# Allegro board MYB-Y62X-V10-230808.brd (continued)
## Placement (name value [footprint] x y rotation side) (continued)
TP5  SMD  [TEST0_8-SMD]  42.08 79.88 0 top
TP6  SMD  [TEST0_8-SMD]  35.84 30.94 0 top
TP7  SMD  [HOLE-TP0_9S16]  47.34 42.34 0 top
TP8  SMD  [TEST0_8-SMD]  37.77 34.16 0 top
TP9  SMD  [HOLE-TP0_9S16]  60.7 44.3 0 top
TP10  SMD  [HOLE-TP0_9S16]  87.55 100.97 0 top
TP14  SMD  [TEST0_8-SMD]  127.17 19.15 0 top
TP15  -  [TPAD_020]  65.99 102.31 0 bottom
TP16  -  [TPAD_020]  74.21 106.51 0 bottom
TP17  SMD  [HOLE-TP0_9S16]  34.46 67.06 0 top
TP18  -  [TPAD_020]  26.97 47.62 180 bottom
TP19  -  [TPAD_020]  32.56 47.62 180 bottom
TP20  -  [TPAD_020]  33.57 47.62 180 bottom
TP21  -  [TPAD_020]  34.59 47.62 0 bottom
TP22  -  [TPAD_020]  39.16 47.62 180 bottom
TP23  -  [TPAD_020]  40.18 47.62 180 bottom
TP24  -  [TPAD_020]  41.19 47.62 180 bottom
TP25  -  [TPAD_020]  42.21 47.62 180 bottom
TP26  -  [TPAD_020]  43.23 47.62 180 bottom
TP27  -  [TPAD_020]  44.5 47.62 180 bottom
TP28  -  [TPAD_020]  45.77 47.62 180 bottom
TP30  SMD  [HOLE-TP0_9S16]  28.88 67.06 0 top
TP31  SMD  [HOLE-TP0_9S16]  83.61 94.87 0 top
TP32  SMD  [HOLE-TP0_9S16]  42.46 35.31 0 top
TP33  SMD  [HOLE-TP0_9S16]  60.73 40.34 0 top
U1  SY8388ARHC  [QFN16_0_45]  38.53 81.15 0 top
U2  SY8388ARHC  [QFN16_0_45]  34.21 35.43 0 top
U3  MP2143DJ-LF-Z  [TSOT23-8]  52.37 39.12 0 top
U4  MP2143DJ-LF-Z  [TSOT23-8]  77.14 96.65 0 top
U8  RS1G08XF5  [SOT23-5]  94.15 112.39 180 top
U12  RS1G32XC5  [SC70-5]  156.26 85.09 0 top
U13  RS1G32XC5  [SC70-5]  156.26 81.28 0 top
U14  PCMF2USB3S  [WLCSP10]  19.73 55.5 90 top
U15  PCMF2USB3S  [WLCSP10]  19.73 67.94 90 top
U16  PCMF3USB3S/CZ  [WLCSP15]  19.73 61.59 90 top
U17  PCMF3USB3S/CZ  [WLCSP15]  19.73 74.17 90 top
U18  RS0102YVS8  [VSSOP8]  156.26 69.47 0 top
U19  CH342F  [QFN24-0_5]  71.11 19.68 90 top
U20  NSI1050-DDBR  [SOP8-2_54]  156.44 100.6 0 top
U21  B0505S-1WR3  [MODULE-B0505S]  166.1 100.6 270 top
U22  NSI1050-DDBR  [SOP8-2_54]  145.01 100.48 0 top
U23  NSI83085A  [SOIC16-W]  132.31 100.48 90 top
U24  B0505S-1WR3  [MODULE-B0505S]  108.06 101.37 270 top
U25  NSI83085A  [SOIC16-W]  119.61 100.48 90 top
U27  SGTL5000XNAA3  [QFN32]  44.75 21.97 0 top
U28  FE1.1-AQFP48AT  [LQFP48]  130.86 29.59 0 top
U29  PTN5150AHXMP  [X2QFN12]  58.21 18.8 90 top
U30  MP62055EJ-LF-Z  [SOT23-5]  59.61 25.4 180 top
U31  SM8103ADC  [SOT23-6]  38.4 65.15 0 top
U32  SR05-04A  [SOT23-6]  85.81 24.36 90 top
U33  YT8531SH  [QFN48-0_4]  89.87 32.36 90 top
U34  SR05-04A  [SOT23-6]  93.43 24.36 90 top
U35  RS1G08XF5  [SOT23-5]  74 38.1 0 top
U36  SR05-04A  [SOT23-6]  108.47 24.36 90 top
U37  YT8531SH  [QFN48-0_4]  113.17 32.36 90 top
U38  SR05-04A  [SOT23-6]  115.45 24.36 90 top
U39  RS1G08XF5  [SOT23-5]  67.99 38.07 0 top
U40  RX-8025T/UC  [SOP14]  122.09 67.82 270 top
U42  NCA9555  [TSSOP24]  142.03 67.31 0 top
U43  AM62x  [MYB-YOUPK43X45_1_00-LGA58]  86.28 68.83 0 top
U45  RS0102YVS8  [VSSOP8]  156.26 73.53 0 top
U46  RS0102YVS8  [VSSOP8]  14.27 109.6 0 top
U47  FGL297BSRX-00  [MODULE-L297B-SR]  55.04 107.01 0 top
U48  SII9022ACNU  [QFN72]  149.14 30.61 270 top
U50  SGM2019-1.2YN5G/TR  [SOT23-5]  149.27 53.72 0 top
U51  PCMF2USB3S  [WLCSP10]  156.8 14.22 180 top
U52  PCMF2USB3S  [WLCSP10]  153.59 14.22 180 top
U53  RS0102YVS8  [VSSOP8]  149.27 49.53 0 top
U54  74CBTLV3257PW  [TSSOP16]  69.84 32.63 180 top
U55  S28HS512TGABHV010  [BGA24]  95.55 100.66 0 top
Y1  12MHz  [3225]  160.25 47.88 90 bottom
Y2  11.2896MHz  [3225]  51.48 22.73 90 top
Y3  12MHz  [3225]  121.97 27.56 270 top
Y4  25MHz  [3225]  81.36 31.09 270 top
Y5  25MHz  [3225]  104.66 31.09 270 top
Y6  DNP  [3225]  53.01 94.31 180 top
Y7  DNP  [3225]  143.56 21.21 0 top

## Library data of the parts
C1-C5 C7-C47 C54-C62 C65 C70-C119 C121-C242 C247-C251 C253 C256-C266 C269-C275 C278-C294 C318-C325 C328-C338 = Ceramic Capacitor
C6 = Aluminum Electrolytic Capacitor
CT1 CT2 = Tantalum Capacitor
D1 D58 D59 = General Diode
D2-D43 D45 D47 D49 D56 D57 = TVS Diode
D44 D46 = Schottky Diode
D48 = BAT54C
D50 = LED-204-10SURD/S530-A3-L
D53-D55 = LED-19-217/BHC-ZL1M2RY/3T
F1-F3 = Fuse
FB1-FB4 FB6-FB16 = Ferrite Bead
J1 = DC-738-032XX009
J2 = TF-CARD
J4 = 2X10PIN
J5 J6 = FPC40
J7 = B6B-PH-K-S
J8 J11 = 2X15PIN
J9 = FPC24
J12 J15 = UT12111-B1609-7F
J13 = 1x12PIN
J14 = JA41131-34BCB-7H
J16 = UB11121-8FDE-4F
J17 J18 = SIM-SI62C
J19 = PCIEXP_CONN67P_KEY_B
J20 = SMA-5PIN
J21 J27 J28 = ANT4-0403
J22 J23 = S11-ZZ-0319
J25 = 1X2PIN
J26 = 1X3PIN
J29 = HDMI
JP1-JP3 = SIP2-DROIT
L1 L7 L8 = COMMON_CHOKE_1
L2-L5 L10-L13 = Inductor
L6 L9 = Common Choke
MTG1-MTG4 = MHOLE_3
MTG6 MTG9-MTG11 = Mounting_Hole_1P
Q1 Q4-Q8 = N-MOSFET
Q2 = NPN Transistor
Q3 = P-MOSFET
R1-R4 R6-R8 R10-R16 R18-R23 R34-R42 R45-R49 R64-R66 R68-R74 R77 R94 R112 R117 R127 R132-R136 R143 R147 R149 R153 R157 R158 R203-R207 R209-R213 R216-R219 R222-R236 R238 R239 R241 R243-R246 R249-R251 R255 R256 R258 R259 R264 R266 R304-R313 R316 R319-R322 R324 R328-R331 R336-R347 R360-R382 R395-R414 R416 R417 R419 R423 R424 R426-R429 R431-R435 R437 R438 R456 R460 R467 R468 R470 R471 R473 R474 R498 R511-R514 R518 R521-R531 R535-R537 R539 R542-R545 R554 R555 R557-R563 R567 R569-R575 = Resister
R5 R9 R17 R43 R44 R50-R63 R76 R78-R85 R92 R103-R111 R113-R116 R118-R126 R128-R131 R137-R142 R144-R146 R148 R150-R152 R154 R156 R159 R161-R186 R190-R192 R194-R196 R198 R208 R220 R221 R237 R240 R242 R252-R254 R257 R260-R263 R265 R267-R270 R272 R274 R280 R281 R283-R285 R288 R290-R295 R298 R302 R314 R315 R317 R318 R323 R325-R327 R332-R335 R348-R359 R383-R394 R444 R445 R449 R451-R454 R461 R487 R489 R491-R494 R502 R504 R515-R517 R532-R534 R540 = Resister: signal model: RESISTER_R0402_0R/4/5%_0R/4/5%
R24-R26 R160 R197 R199-R202 R247 R248 R271 R273 R275-R279 R282 R286 R287 R289 R297 R299-R301 R303 = Resister: signal model: RESISTER_R0402_22R/4/5%_22R/4/5%
S1-S3 = SKRAAME010
SW1 = SS-12D10-L9-B
SW2 SW3 = SWITCH-4
TEMPLATE1 = TEMPLATE-A2
TP1 TP2 TP7 TP9 TP10 TP17 TP30-TP33 = TP_7
TP3 TP5 TP6 TP8 TP14 = TP
TP15 TP16 TP18-TP28 = TESTLOOP
U1 U2 = SY8388ARHC
U3 U4 = MP2143
U8 U35 U39 = 74LVC1G08GW
U12 U13 = RS1G32XC5
U14 U15 U51 U52 = PCMF2USB3S
U16 U17 = PCMF3USB3S
U18 U45 U46 U53 = TXS0102DCT
U19 = CH342F
U20 U22 = NSI1050-DDBR
U21 U24 = B0505S-1W
U23 U25 = ISO3082DW
U27 = SGTL5000
U28 = AQFP48AT
U29 = PTN5150AHXMP
U30 = MP62055E
U31 = SM8103ADC
U32 U34 U36 U38 = TPD4E1U06
U33 U37 = YT8521SH
U40 = RX-8025T
U42 = AT9555PW
U43 = MYC-Y15X_0
U47 = FGL297BSRX-00
U48 = SII9022A
U50 = SGM2019
U54 = SN74CBTLV3257
U55 = Flash-S28HS512TGABHV010
Y1 Y2 Y6 Y7 = Oscillator_4P
Y3-Y5 = Crystal_4P

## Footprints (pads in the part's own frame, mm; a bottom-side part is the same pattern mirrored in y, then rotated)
738-032XX009
  rect 1.6x1.6 hole 1.6 unplated: (0,0)
  oval 3x1.8 hole 2x0.8: 2(6.2,5.3) 3(6.2,0) 4(6.2,-3.2) 5(-1,6.2)
  oval 3x1.6 hole 2x0.6: 6(-1,-3.6)
3225
  oval 1.3x1 smd: 1(-1.15,-0.9) 2(1.15,-0.9) 3(1.15,0.9) 4(-1.15,0.9)
ANT-5PINS
  round 2.1 hole 1.1: 1(0,0)
  round 2.3 hole 1.35: 2(2.54,2.54) 3(2.54,-2.54) 4(-2.54,-2.54) 5(-2.54,2.54)
ANT-1566230-1
  oval 1.1x0.7 smd: 1(-1.35,0) 2(1.35,0)
  oval 2.2x1 smd: 3(0,1.3) 4(0,-1.3)
AUDIO-JA41131-34BCB-7H
  round 1.1 hole 1.1 unplated: (0,0)
  oval 1.3x2.2 hole 0.5x1.4: 1(3.8,3.1) 2(-3.7,-3.5) 3(3.7,-5.6) 4(-4.6,-5.6) 5(-2.2,3.1) 6(-3.8,3.1) 7(4.6,-1.1) 8(-4.6,-1.1)
BGA24
  round 0.33 smd: A2(-1,2) A3(0,2) A4(1,2) A5(2,2) B1(-2,1) B2(-1,1) B3(0,1) B4(1,1) B5(2,1) C1(-2,0) C2(-1,0) C3(0,0) C4(1,0) C5(2,0) D1(-2,-1) D2(-1,-1) D3(0,-1) D4(1,-1) D5(2,-1) E1(-2,-2) E2(-1,-2) E3(0,-2) E4(1,-2) E5(2,-2)
C0402
  custom 0.125x0.125 smd: 1(-0.44,0) 2(0.44,0)
C0603
  oval 0.711x0.914 smd: 1(-0.724,0) 2(0.724,0)
C0805
  oval 0.8x1.3 smd: 1(-0.753,0) 2(0.753,0)
C1206
  oval 1x1.8 smd: 1(-1.45,0) 2(1.45,0)
CE6X6
  oval 1x3.2 smd: 1(0,-2.7) 2(0,2.7)
CONN1X2-1_25-DIP
  rect 0.95x0.95 hole 0.6: 1(0.625,0)
  oval 0.85x0.95 hole 0.6: 2(-0.625,0)
CONN1X2-2_54-DIP
  rect 1.6x1.6 hole 0.9: 1(0,1.27)
  round 1.6 hole 0.9: 2(0,-1.27)
CONN1X3-2_54-DIP
  rect 1.6x1.6 hole 0.9: 1(0,2.54)
  round 1.6 hole 0.9: 2(0,0) 3(0,-2.54)
CONN2X10-1_27
  round 1.05 hole 1.05 unplated: (-5.08,0) (5.08,0)
  oval 0.74x2.4 smd: 1(-5.715,-1.95) 2(-5.715,1.95) 3(-4.445,-1.95) 4(-4.445,1.95) 5(-3.175,-1.95) 6(-3.175,1.95) 7(-1.905,-1.95) 8(-1.905,1.95) 9(-0.635,-1.95) 10(-0.635,1.95) 11(0.635,-1.95) 12(0.635,1.95) 13(1.905,-1.95) 14(1.905,1.95) 15(3.175,-1.95) 16(3.175,1.95) 17(4.445,-1.95) 18(4.445,1.95) 19(5.715,-1.95) 20(5.715,1.95)
CONN2X15-2_00-SMD
  oval 0.991x2.794 smd: 1(-13.999,-2.388) 2(-13.999,2.388) 3(-11.993,-2.388) 4(-11.993,2.388) 5(-10.011,-2.388) 6(-10.011,2.388) 7(-8.005,-2.388) 8(-8.005,2.388) 9(-5.998,-2.388) 10(-5.998,2.388) 11(-3.992,-2.388) 12(-3.992,2.388) 13(-2.01,-2.388) 14(-2.01,2.388) 15(-0.004,-2.388) 16(-0.004,2.388) 17(2.003,-2.388) 18(2.003,2.388) 19(4.009,-2.388) 20(4.009,2.388) 21(5.991,-2.388) 22(5.991,2.388) 23(7.997,-2.388) 24(7.997,2.388) 25(10.004,-2.388) 26(10.004,2.388) 27(12.01,-2.388) 28(12.01,2.388) 29(13.992,-2.388) 30(13.992,2.388)
CONN-2199230-3
  rect 1.194x2.743 smd: (-10.35,3.125) (10.35,3.125)
  round 0.254 hole 1.092 unplated: (-10,-1.375)
  round 0.254 hole 1.6 unplated: (10,-1.375)
  rect 0.305x1.549 smd: 1(-9.25,3.9) 2(-9,-3.65) 3(-8.75,3.9) 4(-8.5,-3.65) 5(-8.25,3.9) 6(-8,-3.65) 7(-7.75,3.9) 8(-7.5,-3.65) 9(-7.25,3.9) 10(-7,-3.65) 11(-6.75,3.9) 20(-4.5,-3.65) 21(-4.25,3.9) 22(-4,-3.65) 23(-3.75,3.9) 24(-3.5,-3.65) 25(-3.25,3.9) 26(-3,-3.65) 27(-2.75,3.9) 28(-2.5,-3.65) 29(-2.25,3.9) 30(-2,-3.65) 31(-1.75,3.9) 32(-1.5,-3.65) 33(-1.25,3.9) 34(-1,-3.65) 35(-0.75,3.9) 36(-0.5,-3.65) 37(-0.25,3.9) 38(0,-3.65) 39(0.25,3.9) 40(0.5,-3.65) 41(0.75,3.9) 42(1,-3.65) 43(1.25,3.9) 44(1.5,-3.65) 45(1.75,3.9) 46(2,-3.65) 47(2.25,3.9) 48(2.5,-3.65) 49(2.75,3.9) 50(3,-3.65) 51(3.25,3.9) 52(3.5,-3.65) 53(3.75,3.9) 54(4,-3.65) 55(4.25,3.9) 56(4.5,-3.65) 57(4.75,3.9) 58(5,-3.65) 59(5.25,3.9) 60(5.5,-3.65) 61(5.75,3.9) 62(6,-3.65) 63(6.25,3.9) 64(6.5,-3.65) 65(6.75,3.9) 66(7,-3.65) 67(7.25,3.9) 68(7.5,-3.65) 69(7.75,3.9) 70(8,-3.65) 71(8.25,3.9) 72(8.5,-3.65) 73(8.75,3.9) 74(9,-3.65) 75(9.25,3.9)
CONN-B6B-PH-K
  rect 1.4x1.8 hole 0.8x1.02: 1(5,0)
  oval 1.4x1.8 hole 0.8x1.02: 2(3,0) 3(1,0) 4(-1,0) 5(-3,0) 6(-5,0)
CT3528-B
  oval 1.5x2.4 smd: 1(-1.65,0) 2(1.65,0)
D0402
  custom 0.125x0.125 smd: 1(-0.44,0) 2(0.44,0)
DO-214AA
  oval 2x2.3 smd: 1(-2.2,0) 2(2.2,0)
DO-214AB
  oval 2.2x3.3 smd: 1(-3.35,0) 2(3.35,0)
F1206
  oval 1x1.7 smd: 1(-1.397,0) 2(1.397,0)
FB0603
  oval 0.7x0.9 smd: 1(-0.65,0) 2(0.65,0)
FPC24-0_5-H
  oval 0.3x1.8 smd: 1(5.75,-0.2) 2(5.25,-0.2) 3(4.75,-0.2) 4(4.25,-0.2) 5(3.75,-0.2) 6(3.25,-0.2) 7(2.75,-0.2) 8(2.25,-0.2) 9(1.75,-0.2) 10(1.25,-0.2) 11(0.75,-0.2) 12(0.25,-0.2) 13(-0.25,-0.2) 14(-0.75,-0.2) 15(-1.25,-0.2) 16(-1.75,-0.2) 17(-2.25,-0.2) 18(-2.75,-0.2) 19(-3.25,-0.2) 20(-3.75,-0.2) 21(-4.25,-0.2) 22(-4.75,-0.2) 23(-5.25,-0.2) 24(-5.75,-0.2)
  rect 1.8x2.6 smd: 25(-8.05,-2.421) 26(8.05,-2.421)
FPC40-0_5-H
  oval 0.3x1.8 smd: 1(9.75,2.3) 2(9.25,2.3) 3(8.75,2.3) 4(8.25,2.3) 5(7.75,2.3) 6(7.25,2.3) 7(6.75,2.3) 8(6.25,2.3) 9(5.75,2.3) 10(5.25,2.3) 11(4.75,2.3) 12(4.25,2.3) 13(3.75,2.3) 14(3.25,2.3) 15(2.75,2.3) 16(2.25,2.3) 17(1.75,2.3) 18(1.25,2.3) 19(0.75,2.3) 20(0.25,2.3) 21(-0.25,2.3) 22(-0.75,2.3) 23(-1.25,2.3) 24(-1.75,2.3) 25(-2.25,2.3) 26(-2.75,2.3) 27(-3.25,2.3) 28(-3.75,2.3) 29(-4.25,2.3) 30(-4.75,2.3) 31(-5.25,2.3) 32(-5.75,2.3) 33(-6.25,2.3) 34(-6.75,2.3) 35(-7.25,2.3) 36(-7.75,2.3) 37(-8.25,2.3) 38(-8.75,2.3) 39(-9.25,2.3) 40(-9.75,2.3)
  rect 1.8x2.2 smd: 41(-12.35,-0.321) 42(12.25,-0.321)
GNDPOINT256
  round 5.08 hole 2.769: 1(0,0)
HOLE3_2P-8
  round 0.85 hole 0.5: 1(1.605,1.605) 2(2.261,0) 3(1.6,-1.6) 4(0,-2.261) 5(-1.6,-1.6) 6(-2.261,0) 7(-1.595,1.595) 8(0,2.261)
  round 3.5 hole 3.2: 9(0,0)
HOLE-TP0_9S16
  rect 1.6x1.6 hole 0.9: 1(0,0)
INDCM-ACM7060
  oval 2.2x1.5 smd: 1(-3,1.5) 2(-3,-1.5) 3(3,-1.5) 4(3,1.5)
INDCM-ACT45B
  oval 1.5x0.95 smd: 1(-1.85,1.202) 2(-1.85,-1.202) 3(1.85,-1.202) 4(1.85,1.202)
INDCM-SDCW2012
  oval 0.8x0.5 smd: 1(-0.8,0.502) 2(0.8,0.502) 3(0.8,-0.502) 4(-0.8,-0.502)
L2X2_5
  oval 1x2 smd: 1(-1,0) 2(1,0)
L3X3
  oval 3x1.2 smd: 1(0,1.22) 2(0,-1.22)
L4_0X4_0
  oval 1x3.5 smd: 1(-1.5,0) 2(1.5,0)
L5_2X5_5
  oval 2.6x1.8 smd: 1(0,2.4) 2(0,-2.4)
LED0603
  oval 0.6x0.8 smd: 1(-0.75,0) 2(0.75,0)
LQFP48
  oval 1.2x0.25 smd: 1(-4.3,2.75) 2(-4.3,2.25) 3(-4.3,1.749) 4(-4.3,1.249) 5(-4.3,0.751) 6(-4.3,0.251) 7(-4.3,-0.25) 8(-4.3,-0.75) 9(-4.3,-1.25) 10(-4.3,-1.751) 11(-4.3,-2.251) 12(-4.3,-2.749) 25(4.3,-2.749) 26(4.3,-2.251) 27(4.3,-1.751) 28(4.3,-1.25) 29(4.3,-0.75) 30(4.3,-0.25) 31(4.3,0.251) 32(4.3,0.751) 33(4.3,1.249) 34(4.3,1.749) 35(4.3,2.25) 36(4.3,2.75)
  oval 0.25x1.2 smd: 13(-2.749,-4.299) 14(-2.251,-4.299) 15(-1.751,-4.299) 16(-1.25,-4.299) 17(-0.75,-4.299) 18(-0.249,-4.299) 19(0.251,-4.299) 20(0.751,-4.299) 21(1.249,-4.299) 22(1.75,-4.299) 23(2.25,-4.299) 24(2.75,-4.299) 37(2.75,4.301) 38(2.25,4.301) 39(1.75,4.301) 40(1.249,4.301) 41(0.751,4.301) 42(0.251,4.301) 43(-0.249,4.301) 44(-0.75,4.301) 45(-1.25,4.301) 46(-1.751,4.301) 47(-2.251,4.301) 48(-2.749,4.301)
MH236-125T
  round 5.994 hole 3.175: 1(0,0)
MODULE-B0505S
  round 1.5 hole 0.7: 1(3.81,2.1) 2(1.27,2.1) 3(-1.27,2.1) 4(-3.81,2.1)
MODULE-L297B-SR
  oval 0.4x1.3 smd: 1(4.5,7.35) 2(3.6,7.35) 3(2.7,7.35) 4(1.8,7.35) 5(0.9,7.35) 6(0,7.35) 7(-0.9,7.35) 8(-1.8,7.35) 9(-2.7,7.35) 10(-3.6,7.35) 11(-4.5,7.35) 26(-4.5,-7.35) 27(-3.6,-7.35) 28(-2.7,-7.35) 29(-1.8,-7.35) 30(-0.9,-7.35) 31(0,-7.35) 32(0.9,-7.35) 33(1.8,-7.35) 34(2.7,-7.35) 35(3.6,-7.35) 36(4.5,-7.35)
  oval 1.3x0.4 smd: 12(-6.35,5.85) 13(-6.35,4.95) 14(-6.35,4.05) 15(-6.35,3.15) 16(-6.35,2.25) 17(-6.35,1.35) 18(-6.35,0.45) 19(-6.35,-0.45) 20(-6.35,-1.35) 21(-6.35,-2.25) 22(-6.35,-3.15) 23(-6.35,-4.05) 24(-6.35,-4.95) 25(-6.35,-5.85) 37(6.35,-5.85) 38(6.35,-4.95) 39(6.35,-4.05) 40(6.35,-3.15) 41(6.35,-2.25) 42(6.35,-1.35) 43(6.35,-0.45) 44(6.35,0.45) 45(6.35,1.35) 46(6.35,2.25) 47(6.35,3.15) 48(6.35,4.05) 49(6.35,4.95) 50(6.35,5.85)
MYB-YOUPK43X45_1_00-LGA58
  oval 1.171x0.6 smd: 1(-21.5,20.5) 2(-21.5,19.5) 3(-21.5,18.5) 4(-21.5,17.5) 5(-21.5,16.5) 6(-21.5,15.5) 7(-21.5,14.5) 8(-21.5,13.5) 9(-21.5,12.5) 10(-21.5,11.5) 11(-21.5,10.5) 12(-21.5,9.5) 13(-21.5,8.5) 14(-21.5,7.5) 15(-21.5,6.5) 16(-21.5,5.5) 17(-21.5,4.5) 18(-21.5,3.5) 19(-21.5,2.5) 20(-21.5,1.5) 21(-21.5,0.5) 22(-21.5,-0.5) 23(-21.5,-1.5) 24(-21.5,-2.5) 25(-21.5,-3.5) 26(-21.5,-4.5) 27(-21.5,-5.5) 28(-21.5,-6.5) 29(-21.5,-7.5) 30(-21.5,-8.5) 31(-21.5,-9.5) 32(-21.5,-10.5) 33(-21.5,-11.5) 34(-21.5,-12.5) 35(-21.5,-13.5) 36(-21.5,-14.5) 37(-21.5,-15.5) 38(-21.5,-16.5) 39(-21.5,-17.5) 40(-21.5,-18.5) 41(-21.5,-19.5) 42(-21.5,-20.5) 83(21.5,-20.5) 84(21.5,-19.5) 85(21.5,-18.5) 86(21.5,-17.5) 87(21.5,-16.5) 88(21.5,-15.5) 89(21.5,-14.5) 90(21.5,-13.5) 91(21.5,-12.5) 92(21.5,-11.5) 93(21.5,-10.5) 94(21.5,-9.5) 95(21.5,-8.5) 96(21.5,-7.5) 97(21.5,-6.5) 98(21.5,-5.5) 99(21.5,-4.5) 100(21.5,-3.5) 101(21.5,-2.5) 102(21.5,-1.5) 103(21.5,-0.5) 104(21.5,0.5) 105(21.5,1.5) 106(21.5,2.5) 107(21.5,3.5) 108(21.5,4.5) 109(21.5,5.5) 110(21.5,6.5) 111(21.5,7.5) 112(21.5,8.5) 113(21.5,9.5) 114(21.5,10.5) 115(21.5,11.5) 116(21.5,12.5) 117(21.5,13.5) 118(21.5,14.5) 119(21.5,15.5) 120(21.5,16.5) 121(21.5,17.5) 122(21.5,18.5) 123(21.5,19.5) 124(21.5,20.5)
  oval 0.6x1.171 smd: 43(-19.5,-22.5) 44(-18.5,-22.5) 45(-17.5,-22.5) 46(-16.5,-22.5) 47(-15.5,-22.5) 48(-14.5,-22.5) 49(-13.5,-22.5) 50(-12.5,-22.5) 51(-11.5,-22.5) 52(-10.5,-22.5) 53(-9.5,-22.5) 54(-8.5,-22.5) 55(-7.5,-22.5) 56(-6.5,-22.5) 57(-5.5,-22.5) 58(-4.5,-22.5) 59(-3.5,-22.5) 60(-2.5,-22.5) 61(-1.5,-22.5) 62(-0.5,-22.5) 63(0.5,-22.5) 64(1.5,-22.5) 65(2.5,-22.5) 66(3.5,-22.5) 67(4.5,-22.5) 68(5.5,-22.5) 69(6.5,-22.5) 70(7.5,-22.5) 71(8.5,-22.5) 72(9.5,-22.5) 73(10.5,-22.5) 74(11.5,-22.5) 75(12.5,-22.5) 76(13.5,-22.5) 77(14.5,-22.5) 78(15.5,-22.5) 79(16.5,-22.5) 80(17.5,-22.5) 81(18.5,-22.5) 82(19.5,-22.5) 125(19.5,22.5) 126(18.5,22.5) 127(17.5,22.5) 128(16.5,22.5) 129(15.5,22.5) 130(14.5,22.5) 131(13.5,22.5) 132(12.5,22.5) 133(11.5,22.5) 134(10.5,22.5) 135(9.5,22.5) 136(8.5,22.5) 137(7.5,22.5) 138(6.5,22.5) 139(5.5,22.5) 140(4.5,22.5) 141(3.5,22.5) 142(2.5,22.5) 143(1.5,22.5) 144(0.5,22.5) 145(-0.5,22.5) 146(-1.5,22.5) 147(-2.5,22.5) 148(-3.5,22.5) 149(-4.5,22.5) 150(-5.5,22.5) 151(-6.5,22.5) 152(-7.5,22.5) 153(-8.5,22.5) 154(-9.5,22.5) 155(-10.5,22.5) 156(-11.5,22.5) 157(-12.5,22.5) 158(-13.5,22.5) 159(-14.5,22.5) 160(-15.5,22.5) 161(-16.5,22.5) 162(-17.5,22.5) 163(-18.5,22.5) 164(-19.5,22.5)
  round 1 smd: L1(-17.78,19.05) L2(-17.78,16.51) L3(-17.78,13.97) L4(-17.78,11.43) L5(-17.78,8.89) L6(-17.78,6.35) L7(-17.78,3.81) L8(-17.78,1.27) L9(-17.78,-1.27) L10(-17.78,-3.81) L11(-17.78,-6.35) L12(-17.78,-8.89) L13(-17.78,-11.43) L14(-17.78,-13.97) L15(-17.78,-16.51) L16(-17.78,-19.05) L17(-15.24,-19.05) L18(-12.7,-19.05) L19(-10.16,-19.05) L20(-7.62,-19.05) L21(-5.08,-19.05) L22(-2.54,-19.05) L23(0,-19.05) L24(2.54,-19.05) L25(5.08,-19.05) L26(7.62,-19.05) L27(10.16,-19.05) L28(12.7,-19.05) L29(15.24,-19.05) L30(17.78,-19.05) L31(17.78,-16.51) L32(17.78,-13.97) L33(17.78,-11.43) L34(17.78,-8.89) L35(17.78,-6.35) L36(17.78,-3.81) L37(17.78,-1.27) L38(17.78,1.27) L39(17.78,3.81) L40(17.78,6.35) L41(17.78,8.89) L42(17.78,11.43) L43(17.78,13.97) L44(17.78,16.51) L45(17.78,19.05) L46(15.24,19.05) L47(12.7,19.05) L48(10.16,19.05) L49(7.62,19.05) L50(5.08,19.05) L51(2.54,19.05) L52(0,19.05) L53(-2.54,19.05) L54(-5.08,19.05) L55(-7.62,19.05) L56(-10.16,19.05) L57(-12.7,19.05) L58(-15.24,19.05)
QFN16_0_45
  oval 0.65x0.25 smd: 1(-1.2,0.675) 2(-1.2,0.225) 3(-1.2,-0.225) 4(-1.2,-0.675) 9(1.2,-0.675) 10(1.2,-0.225) 11(1.2,0.225) 12(1.2,0.675)
  oval 0.25x0.65 smd: 5(-0.675,-1.2) 6(-0.225,-1.2) 7(0.225,-1.2) 8(0.675,-1.2) 13(0.675,1.2) 14(0.225,1.2) 15(-0.225,1.2) 16(-0.675,1.2)
  rect 1x1 smd: 17(0,0)
QFN24-0_5
  oval 0.7x0.25 smd: 1(-1.9,1.25) 2(-1.9,0.75) 3(-1.9,0.25) 4(-1.9,-0.25) 5(-1.9,-0.75) 6(-1.9,-1.25) 13(1.9,-1.25) 14(1.9,-0.75) 15(1.9,-0.25) 16(1.9,0.25) 17(1.9,0.75) 18(1.9,1.25)
  oval 0.25x0.7 smd: 7(-1.25,-1.9) 8(-0.75,-1.9) 9(-0.25,-1.9) 10(0.25,-1.9) 11(0.75,-1.9) 12(1.25,-1.9) 19(1.25,1.9) 20(0.75,1.9) 21(0.25,1.9) 22(-0.25,1.9) 23(-0.75,1.9) 24(-1.25,1.9)
  rect 2.7x2.7 smd: 25(0,0)
QFN32
  oval 0.7x0.25 smd: 1(-2.325,1.75) 2(-2.325,1.25) 3(-2.325,0.75) 4(-2.325,0.25) 5(-2.325,-0.25) 6(-2.325,-0.75) 7(-2.325,-1.25) 8(-2.325,-1.75) 17(2.325,-1.75) 18(2.325,-1.25) 19(2.325,-0.75) 20(2.325,-0.25) 21(2.325,0.25) 22(2.325,0.75) 23(2.325,1.25) 24(2.325,1.75)
  oval 0.25x0.7 smd: 9(-1.75,-2.325) 10(-1.25,-2.325) 11(-0.75,-2.325) 12(-0.25,-2.325) 13(0.25,-2.325) 14(0.75,-2.325) 15(1.25,-2.325) 16(1.75,-2.325) 25(1.75,2.325) 26(1.25,2.325) 27(0.75,2.325) 28(0.25,2.325) 29(-0.25,2.325) 30(-0.75,2.325) 31(-1.25,2.325) 32(-1.75,2.325)
  rect 3.1x3.1 smd: 33(0,0)
QFN48-0_4
  oval 0.8x0.2 smd: 1(-3,2.2) 2(-3,1.8) 3(-3,1.4) 4(-3,1) 5(-3,0.6) 6(-3,0.2) 7(-3,-0.2) 8(-3,-0.6) 9(-3,-1) 10(-3,-1.4) 11(-3,-1.8) 12(-3,-2.2) 25(3,-2.2) 26(3,-1.8) 27(3,-1.4) 28(3,-1) 29(3,-0.6) 30(3,-0.2) 31(3,0.2) 32(3,0.6) 33(3,1) 34(3,1.4) 35(3,1.8) 36(3,2.2)
  oval 0.2x0.8 smd: 13(-2.2,-3) 14(-1.8,-3) 15(-1.4,-3) 16(-1,-3) 17(-0.6,-3) 18(-0.2,-3) 19(0.2,-3) 20(0.6,-3) 21(1,-3) 22(1.4,-3) 23(1.8,-3) 24(2.2,-3) 37(2.2,3) 38(1.8,3) 39(1.4,3) 40(1,3) 41(0.6,3) 42(0.2,3) 43(-0.2,3) 44(-0.6,3) 45(-1,3) 46(-1.4,3) 47(-1.8,3) 48(-2.2,3)
  custom 1.075x1.075 smd: 49(-0.1,-0.1)
QFN72
  oval 0.6x0.25 smd: 1(-4.828,4.251) 2(-4.828,3.751) 3(-4.828,3.251) 4(-4.828,2.751) 5(-4.828,2.251) 6(-4.828,1.751) 7(-4.828,1.25) 8(-4.828,0.75) 9(-4.828,0.25) 10(-4.828,-0.25) 11(-4.828,-0.75) 12(-4.828,-1.25) 13(-4.828,-1.751) 14(-4.828,-2.251) 15(-4.828,-2.751) 16(-4.828,-3.251) 17(-4.828,-3.751) 18(-4.828,-4.251) 37(4.828,-4.251) 38(4.828,-3.751) 39(4.828,-3.251) 40(4.828,-2.751) 41(4.828,-2.251) 42(4.828,-1.751) 43(4.828,-1.25) 44(4.828,-0.75) 45(4.828,-0.25) 46(4.828,0.25) 47(4.828,0.75) 48(4.828,1.25) 49(4.828,1.751) 50(4.828,2.251) 51(4.828,2.751) 52(4.828,3.251) 53(4.828,3.751) 54(4.828,4.251)
  oval 0.25x0.6 smd: 19(-4.251,-4.828) 20(-3.751,-4.828) 21(-3.251,-4.828) 22(-2.751,-4.828) 23(-2.251,-4.828) 24(-1.751,-4.828) 25(-1.25,-4.828) 26(-0.75,-4.828) 27(-0.25,-4.828) 28(0.25,-4.828) 29(0.75,-4.828) 30(1.25,-4.828) 31(1.751,-4.828) 32(2.251,-4.828) 33(2.751,-4.828) 34(3.251,-4.828) 35(3.751,-4.828) 36(4.251,-4.828) 55(4.251,4.828) 56(3.751,4.828) 57(3.251,4.828) 58(2.751,4.828) 59(2.251,4.828) 60(1.751,4.828) 61(1.25,4.828) 62(0.75,4.828) 63(0.25,4.828) 64(-0.25,4.828) 65(-0.75,4.828) 66(-1.25,4.828) 67(-1.751,4.828) 68(-2.251,4.828) 69(-2.751,4.828) 70(-3.251,4.828) 71(-3.751,4.828) 72(-4.251,4.828)
  rect 5.1x5.1 smd: 73(0,0)
QJ51191-LFB4
  oval 0.28x2.6 smd: 1(4.5,3.74) 2(4,3.74) 3(3.5,3.74) 4(3,3.74) 5(2.5,3.74) 6(2,3.74) 7(1.5,3.74) 8(1,3.74) 9(0.5,3.74) 10(0,3.74) 11(-0.5,3.74) 12(-1,3.74) 13(-1.5,3.74) 14(-2,3.74) 15(-2.5,3.74) 16(-3,3.74) 17(-3.5,3.74) 18(-4,3.74) 19(-4.5,3.74)
  oval 1.6x3.4 hole 1x2.7: 20(-7.25,2.98) 23(7.25,2.98)
  oval 1.6x2.8 hole 1x2.1: 21(-7.25,-2.98) 22(7.25,-2.98)
R0402
  custom 0.125x0.125 smd: 1(-0.44,0) 2(0.44,0)
R0603
  oval 0.7x0.9 smd: 1(-0.724,0) 2(0.724,0)
R1206
  oval 1x1.65 smd: 1(-1.3,0) 2(1.3,0)
S11-ZZ-0319
  round 3.25 hole 3.25 unplated: (-5.715,0) (5.715,0)
  round 1.8 hole 0.9: 1(-5.715,8.89) 2(-4.445,6.35) 3(-3.175,8.89) 4(-1.905,6.35) 5(-0.635,8.89) 6(0.635,6.35) 7(1.905,8.89) 8(3.175,6.35) 9(4.445,8.89) 10(5.715,6.35) 11(6.325,-3.38) 12(3.785,-4.9) 13(-3.785,-3.38) 14(-6.325,-4.9)
  round 2.6 hole 1.6: 15(7.775,3.05) 16(-7.775,3.05)
SC70-5
  oval 0.8x0.3 smd: 1(-0.975,0.65) 2(-0.975,0) 3(-0.975,-0.65) 4(0.975,-0.65) 5(0.975,0.65)
SD-MR01A-01211
  round 0.9 hole 0.9 unplated: (-4.85,-3.1) (3.15,-3.1)
  oval 0.7x1.8 smd: 1(2.35,7.4) 2(1.25,7.4) 3(0.15,7.4) 4(-0.95,7.4) 5(-2.05,7.4) 6(-3.15,7.4) 7(-4.25,7.4) 8(-5.35,7.4) 9(-6.45,7.4)
  oval 1.6x1.5 smd: 10(-7.9,6.85) 11(7.25,6.9)
  oval 1.8x1.5 smd: 12(-7.75,-2.7) 13(7.85,-2.7)
SIM-SI62C-01200
  oval 0.8x1.5 smd: 1(-5.018,8.697) 2(-2.478,8.697) 3(0.062,8.697) 4(1.332,8.697) 5(-6.288,8.697) 6(-3.748,8.697) 7(-1.208,8.697)
  rect 1.5x2.3 smd: 8(-7.9,6.25) 9(7.9,6.25) 10(-7.9,-6.25) 11(7.9,-6.25)
SKRAAME010
  oval 2.75x1 smd: 1(2.875,2) 2(-2.875,2) 3(2.875,-2) 4(-2.875,-2)
SOD123
  oval 1.2x1 smd: 1(-1.5,0) 2(1.5,0)
SOD323
  oval 0.9x0.7 smd: 1(1.07,0) 2(-1.07,0)
SOIC16-W
  oval 2.2x0.5 smd: 1(-4.8,4.445) 2(-4.8,3.175) 3(-4.8,1.905) 4(-4.8,0.635) 5(-4.8,-0.635) 6(-4.8,-1.905) 7(-4.8,-3.175) 8(-4.8,-4.445) 9(4.8,-4.445) 10(4.8,-3.175) 11(4.8,-1.905) 12(4.8,-0.635) 13(4.8,0.635) 14(4.8,1.905) 15(4.8,3.175) 16(4.8,4.445)
SOP8-2_54
  oval 0.8x2.4 smd: 1(-3.81,-4.655) 2(-1.27,-4.655) 3(1.27,-4.655) 4(3.81,-4.655) 5(3.81,4.655) 6(1.27,4.655) 7(-1.27,4.655) 8(-3.81,4.655)
SOP14
  oval 0.6x1.8 smd: 1(-3.81,-3.355) 2(-2.54,-3.355) 3(-1.27,-3.355) 4(0,-3.355) 5(1.27,-3.355) 6(2.54,-3.355) 7(3.81,-3.355) 8(3.81,3.355) 9(2.54,3.355) 10(1.27,3.355) 11(0,3.355) 12(-1.27,3.355) 13(-2.54,3.355) 14(-3.81,3.355)
SOT23-5
  oval 1.2x0.5 smd: 1(-1.15,0.95) 2(-1.15,0) 3(-1.15,-0.95) 4(1.15,-0.95) 5(1.15,0.95)
SOT23-6
  oval 1.3x0.4 smd: 1(-1.2,0.95) 2(-1.2,0) 3(-1.2,-0.95) 4(1.2,-0.95) 5(1.2,0) 6(1.2,0.95)
SOT-23
  oval 0.95x1.2 smd: 1(-0.966,-0.993) 2(0.966,-0.993) 3(0,0.893)
SW-2X4
  oval 0.8x1.8 smd: 1(-1.91,-4.01) 2(-0.63,-4.01) 3(0.63,-4.01) 4(1.91,-4.01) 5(1.91,4.01) 6(0.63,4.01) 7(-0.63,4.01) 8(-1.91,4.01)
SW-SS-12D10-L9-B
  oval 2.3x3 hole 1.3x1.8: 1(-4.7,0) 2(0,0) 3(4.7,0)
TEMPLATE-A2
  round 0 smd: 1(393.7,-5.08)
TEST0_8-SMD
  round 0.8 smd: 1(0,0)
TP381-12PINS-90-W
  rect 2.2x2.2 hole 1.2: 1(20.95,-3.402)
  round 2.2 hole 1.2: 2(17.14,-3.402) 3(13.33,-3.402) 4(9.52,-3.402) 5(5.71,-3.402) 6(1.9,-3.402) 7(-1.91,-3.402) 8(-5.72,-3.402) 9(-9.53,-3.402) 10(-13.34,-3.402) 11(-17.15,-3.402) 12(-20.96,-3.402)
TPAD_020
  round 0.508 smd: 1(0,0)
TSOT23-8
  oval 1x0.3 smd: 1(-1.35,1) 2(-1.35,0.35) 3(-1.35,-0.3) 4(-1.35,-0.95) 5(1.35,-0.95) 6(1.35,-0.3) 7(1.35,0.35) 8(1.35,1)
TSSOP16
  oval 1.6x0.27 smd: 1(-2.9,2.275) 2(-2.9,1.625) 3(-2.9,0.975) 4(-2.9,0.325) 5(-2.9,-0.325) 6(-2.9,-0.975) 7(-2.9,-1.625) 8(-2.9,-2.275) 9(2.9,-2.275) 10(2.9,-1.625) 11(2.9,-0.975) 12(2.9,-0.325) 13(2.9,0.325) 14(2.9,0.975) 15(2.9,1.625) 16(2.9,2.275)
TSSOP24
  oval 1.5x0.25 smd: 1(-2.91,3.575) 2(-2.91,2.925) 3(-2.91,2.275) 4(-2.91,1.625) 5(-2.91,0.975) 6(-2.91,0.325) 7(-2.91,-0.325) 8(-2.91,-0.975) 9(-2.91,-1.625) 10(-2.91,-2.275) 11(-2.91,-2.925) 12(-2.91,-3.575) 13(2.91,-3.575) 14(2.91,-2.925) 15(2.91,-2.275) 16(2.91,-1.625) 17(2.91,-0.975) 18(2.91,-0.325) 19(2.91,0.325) 20(2.91,0.975) 21(2.91,1.625) 22(2.91,2.275) 23(2.91,2.925) 24(2.91,3.575)
UB11121-8FDE-4F
  round 3.2 hole 2.2: 1(-6.57,-1.5) 2(-6.57,-7.2) 3(6.57,-7.2) 4(6.57,-1.5)
  round 1.6 hole 0.92: A1(3.5,-6.83) A2(1,-6.83) A3(-1,-6.83) A4(-3.5,-6.83) B1(3.5,-4.21) B2(1,-4.21) B3(-1,-4.21) B4(-3.5,-4.21)
unnamed
  round 3 hole 3 unplated: (0,0)
unnamed#3
  round 1.016 smd: 1(0,0)
UT12111-B1609-7F
  round 0.55 hole 0.55 unplated: (-3.4,2) (3.4,2)
  oval 0.25x1.25 smd: A1(-2.62,4.105) A2(-2.12,4.105) A3(-1.62,4.105) A4(-1.12,4.105) A5(-0.62,4.105) A6(-0.12,4.105) A7(0.38,4.105) A8(0.88,4.105) A9(1.38,4.105) A10(1.88,4.105) A11(2.38,4.105) A12(2.88,4.105)
  oval 0.25x1 smd: B1(2.62,2.6) B2(2.12,2.6) B3(1.62,2.6) B4(1.12,2.6) B5(0.62,2.6) B6(0.12,2.6) B7(-0.38,2.6) B8(-0.88,2.6) B9(-1.38,2.6) B10(-1.88,2.6) B11(-2.38,2.6) B12(-2.88,2.6)
  oval 1.6x2.8 hole 0.6x1.8: SH1(-4.32,-1.2) SH2(4.32,-1.2)
  oval 1.5x2.5 hole 0.6x1.6: SH3(-4.32,3.35) SH4(4.32,3.35)
  oval 1.5x0.9 hole 1.2x0.6: SH5(-3.99,2.85) SH6(3.99,2.85)
VSSOP8
  oval 0.9x0.22 smd: 1(-1.5,0.75) 2(-1.5,0.25) 3(-1.5,-0.25) 4(-1.5,-0.75) 5(1.5,-0.75) 6(1.5,-0.25) 7(1.5,0.25) 8(1.5,0.75)
WLCSP10
  round 0.25 smd: A1(-0.6,0.4) A2(-0.2,0.4) A3(0.2,0.4) A4(0.6,0.4) B1(-0.4,0) B2(0.4,0) C1(-0.6,-0.4) C2(-0.2,-0.4) C3(0.2,-0.4) C4(0.6,-0.4)
WLCSP15
  round 0.203 smd: A1(-1,0.4) A2(-0.6,0.4) A3(-0.2,0.4) A4(0.2,0.4) A5(0.6,0.4) A6(1,0.4) B1(-0.8,0) B2(0,0) B3(0.8,0) C1(-1,-0.4) C2(-0.6,-0.4) C3(-0.2,-0.4) C4(0.2,-0.4) C5(0.6,-0.4) C6(1,-0.4)
X2QFN12
  oval 0.65x0.2 smd: 1(-0.7,0.2) 2(-0.7,-0.2) 7(0.7,-0.2) 8(0.7,0.2)
  oval 0.2x0.45 smd: 3(-0.6,-0.75) 4(-0.2,-0.75) 5(0.2,-0.75) 6(0.6,-0.75) 9(0.6,0.75) 10(0.2,0.75) 11(-0.2,0.75) 12(-0.6,0.75)

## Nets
AVCC_1V2: C291.1 C292.1 FB15.1 U48.60(AVCC12#60) U48.66(AVCC12#66)
DVDD_RGMII1: C209.1 C210.1 R346.1 R347.1 R368.1 R369.1 R371.1 U33.29(DVDD_RGMII)
DVDD_RGMII2: C228.1 C229.1 R381.1 R382.1 R403.1 R404.1 R406.1 U37.29(DVDD_RGMII)
GND: C1.2 C2.2 C3.2 C4.2 C5.2 C6.2(N) C7.2 C8.2 C9.2 C10.2 C12.2 C13.2 C14.2 C15.2 C16.2 C17.2 C18.2 C20.2 C21.2 C22.2 C23.2 C24.2 C26.2 C27.2 C28.2 C29.2 C30.2 C32.2 C33.2 C34.2 C35.2 C38.2 C39.2 C40.2 C41.2 C42.2 C43.2 C44.2 C45.2 C46.2 C47.2 C54.2 C55.2 C56.2 C57.2 C58.2 C59.2 C60.2 C61.2 C62.2 C65.2 C70.2 C71.2 C72.2 C73.2 C74.2 C75.2 C76.2 C77.2 C79.2 C80.2 C81.2 C82.2 C83.2 C84.2 C85.2 C86.2 C87.2 C88.2 C89.2 C90.2 C91.2 C92.2 C93.2 C94.2 C95.2 C96.2 C97.2 C98.2 C99.1 C100.2 C101.2 C105.2 C107.1 C108.2 C109.2 C113.2 C115.2 C116.2 C119.1 C121.2 C122.2 C125.2 C126.2 C133.2 C134.2 C137.2 C138.2 C139.2 C140.2 C141.2 C142.2 C143.2 C144.2 C145.2 C146.2 C147.2 C148.2 C149.2 C150.2 C151.2 C152.2 C153.2 C154.2 C155.2 C156.2 C157.2 C158.2 C159.2 C160.2 C161.2 C162.2 C163.2 C164.2 C165.1 C166.2 C167.2 C168.2 C169.2 C170.1 C172.2 C173.2 C174.2 C175.2 C176.2 C178.2 C179.2 C180.2 C181.2 C182.2 C183.2 C184.2 C185.2 C186.2 C187.2 C188.2 C189.2 C190.2 C191.2 C192.2 C193.2 C194.2 C195.2 C196.2 C197.2 C198.2 C199.2 C200.2 C201.2 C202.2 C203.2 C204.2 C205.2 C206.2 C207.2 C208.2 C209.2 C210.2 C211.2 C212.2 C213.2 C214.2 C215.2 C216.2 C217.2 C218.2 C219.2 C220.2 C221.2 C222.2 C223.2 C224.2 C225.2 C226.2 C227.2 C228.2 C229.2 C230.2 C231.2 C232.2 C233.2 C234.2 C235.2 C236.2 C237.2 C238.2 C239.2 C240.2 C241.2 C242.2 C247.2 C248.2 C249.2 C250.2 C251.2 C253.2 C256.2 C257.2 C258.2 C259.2 C260.2 C261.2 C262.2 C263.2 C264.2 C265.2 C266.2 C269.2 C270.2 C271.2 C272.2 C273.2 C274.2 C275.2 C278.2 C279.2 C280.2 C281.2 C282.2 C283.2 C284.2 C285.2 C286.2 C287.2 C288.2 C289.2 C290.2 C291.2 C292.2 C293.2 C294.2 C318.2 C319.2 C320.2 C323.2 C324.2 C325.2 C328.2 C329.2 C330.2 C331.2 C332.2 C333.2 C334.2 C335.2 C336.2 C337.2 C338.2 D2.1 D3.1 D4.1 D5.1 D6.1 D7.1 D8.1 D9.1 D10.1 D11.1 D12.1 D13.1 D22.1 D23.1 D24.1 D25.1 D26.1 D27.1 D28.1 D29.1 D30.1 D31.1 D32.1 D33.1 D34.1 D35.1 D36.1 D37.1 D38.1 D39.1 D40.1 D41.1 D42.1 D43.1 D45.1 D47.1 D49.1 D50.2(K) D56.1 D57.1 FB6.1 J2.6(VSS) J2.10(GND) J2.11(SH1) J2.12(SH2) J2.13(SH3) J4.10 J4.12 J4.16 J4.20 J5.7(GND2) J5.10(GND3) J5.13(GND4) J5.16(GND5) J5.19(GND6) J5.22(GND7) J5.25(GND8) J5.30(GND9) J5.41(AGND) J5.42(GND1) J6.7(GND2) J6.10(GND3) J6.13(GND4) J6.16(GND5) J6.19(GND6) J6.22(GND7) J6.25(GND8) J6.30(GND9) J6.41(AGND) J6.42(GND1) J7.1 J7.2 J8.4 J8.5 J8.6 J8.13 J8.14 J8.25 J8.26 J9.8 J9.10 J9.13 J9.16 J9.19 J9.22 J9.25 J9.26 J11.3 J11.4 J11.13 J11.14 J11.23 J11.24 J12.A1(GND1) J12.A12(GND2) J12.B1(GND4) J12.B12(GND3) J15.A1(GND1) J15.A12(GND2) J15.B1(GND4) J15.B12(GND3) J16.A4(GND#A4) J16.B4(GND#B4) J17.5(GND#5) J17.8(GND#8) J17.9(GND#9) J17.10(GND#10) J17.11(GND#11) J18.5(GND#5) J18.8(GND#8) J18.9(GND#9) J18.10(GND#10) J18.11(GND#11) J19.3(IO_3) J19.5(IO_5) J19.11(IO_11) J19.27(IO_27) J19.33(IO_33) J19.39(IO_39) J19.45(IO_45) J19.51(IO_51) J19.57(IO_57) J19.71(IO_71) J19.73(IO_73) J20.2(SHIELD2) J20.3(SHIELD1) J20.4(SHIELD3) J20.5(SHIELD4) J21.3(GND1) J21.4(GND2) J25.2 J26.3 J27.3(GND1) J27.4(GND2) J28.3(GND1) J28.4(GND2) J29.2(SHIELD0) J29.5(SHIELD1) J29.8(SHIELD2) J29.11(SHIELD3) J29.17(GND) L1.3 MTG6.1 MTG9.1 MTG10.1 MTG11.1 Q4.2(S) Q5.2(S) R1.2 R2.2 R6.2 R9.2 R15.2 R16.2 R19.2 R20.2 R22.2 R24.2 R25.2 R26.2 R50.1 R66.2 R92.2 R132.2 R232.2 R233.2 R234.2 R235.2 R236.2 R237.2 R238.2 R239.2 R240.2 R241.2 R242.2 R243.2 R244.2 R245.2 R246.2 R247.2 R249.2 R250.2 R251.1 R259.1 R276.2 R277.1 R287.2 R299.2 R302.2 R307.2 R313.2 R320.1 R321.2 R329.2 R330.2 R343.2 R362.2 R366.2 R367.2 R372.2 R373.2 R374.2 R375.2 R376.2 R377.2 R378.2 R397.2 R401.2 R402.2 R407.2 R408.2 R409.2 R410.2 R411.2 R412.2 R413.2 R419.2 R513.2 R515.2 R517.2 R518.2 R525.2 R526.1 R527.2 R545.2 R555.2 R567.2 R574.2 R575.2 S1.1 S1.2 S2.1 S2.2 S3.1 S3.2 TP1.1(TP) TP30.1(TP) TP31.1(TP) TP32.1(TP) TP33.1(TP) U1.6(GND#6) U1.14(GND#14) U1.17(PGND) U2.6(GND#6) U2.14(GND#14) U2.17(PGND) U3.4(PGND) U3.6(AGND) U4.4(PGND) U4.6(AGND) U8.3(GND) U12.3(GND) U13.3(GND) U14.B1(GND_CH1) U14.B2(GND_CH2) U15.B1(GND_CH1) U15.B2(GND_CH2) U16.B1(GND_CH1) U16.B2(GND_CH2) U16.B3(GND_CH3) U17.B1(GND_CH1) U17.B2(GND_CH2) U17.B3(GND_CH3) U18.2(GND) U19.2(GND) U19.25(EPAD) U20.4(GND1) U21.1(GND) U22.4(GND1) U23.2(GND1#2) U23.7(GND1#7) U23.8(GND1#8) U24.1(GND) U25.2(GND1#2) U25.7(GND1#7) U25.8(GND1#8) U27.1(GND1) U27.3(GND2) U27.32(CTRL_MODE) U27.33(GND3-PAD) U28.1(OVCB2) U28.5(OVCB3) U28.6(VSS#6) U28.7(OVCB4) U28.8(PWRB4) U28.10(VS_PLL) U28.16(VSS#16) U28.22(VSS#22) U28.25(VS_A) U28.33(VSS#33) U29.10(GND) U30.2(GND) U31.2(GND) U32.2(GND) U33.38(HSIP) U33.39(HSIN) U33.49(GND) U34.2(GND) U35.3(GND) U36.2(GND) U37.38(HSIP) U37.39(HSIN) U37.49(GND) U38.2(GND) U39.3(GND) U40.4(NC#4) U40.8(NC#8) U40.9(NC#9) U40.11(GND) U40.14(NC#14) U42.2(A1) U42.3(A2) U42.12(GND) U42.21(A0) U43.1 U43.2 U43.3 U43.9 U43.12 U43.15 U43.18 U43.21 U43.24 U43.27 U43.30 U43.33 U43.36 U43.39 U43.48 U43.51 U43.54 U43.57 U43.60 U43.69 U43.78 U43.91 U43.100 U43.109 U43.119 U43.134 U43.143 U43.152 U45.2(GND) U46.2(GND) U47.1(GND#1) U47.3(GND#3) U47.4(GND#4) U47.5(GND#5) U47.6(GND#6) U47.7(GND#7) U47.8(GND#8) U47.10(GND#10) U47.11(GND#11) U47.23(GND#23) U47.32(GND#32) U47.39(GND#39) U48.43(CGND) U48.55(RSVDL) U48.57(IOGND) U48.63(AGND) U48.70(VDDQ) U48.73(EPAD) U50.2(GND) U51.B1(GND_CH1) U51.B2(GND_CH2) U52.B1(GND_CH1) U52.B2(GND_CH2) U53.2(GND) U54.8(GND) U55.B3(VSS) U55.C1(VSSQ#C1) U55.E5(VSSQ#E5) Y1.2(GND) Y2.2(GND) Y3.2(GND/NC#2) Y3.4(GND/NC#4) Y4.2(GND/NC#2) Y4.4(GND/NC#4) Y5.2(GND/NC#2) Y5.4(GND/NC#4) Y6.2(GND) Y7.2(GND)
GND_EARTH: C7.1 C8.1 C99.2 C165.2 C170.2 C204.1 C223.1 C279.1 J1.5 J1.6 J12.SH1 J12.SH2 J12.SH3 J12.SH4 J12.SH5 J12.SH6 J15.SH1 J15.SH2 J15.SH3 J15.SH4 J15.SH5 J15.SH6 J16.1(BODY1) J16.2(BODY2) J16.3(BODY3) J16.4(BODY4) J22.15(GND1) J22.16(GND2) J23.15(GND1) J23.16(GND2) J29.20(GND0) J29.21(GND3) J29.22(GND1) J29.23(GND2) MTG1.1(GND1) MTG1.2(GND2) MTG1.3(GND3) MTG1.4(GND4) MTG1.5(GND5) MTG1.6(GND6) MTG1.7(GND7) MTG1.8(GND8) MTG1.9(GND9) MTG2.1(GND1) MTG2.2(GND2) MTG2.3(GND3) MTG2.4(GND4) MTG2.5(GND5) MTG2.6(GND6) MTG2.7(GND7) MTG2.8(GND8) MTG2.9(GND9) MTG3.1(GND1) MTG3.2(GND2) MTG3.3(GND3) MTG3.4(GND4) MTG3.5(GND5) MTG3.6(GND6) MTG3.7(GND7) MTG3.8(GND8) MTG3.9(GND9) MTG4.1(GND1) MTG4.2(GND2) MTG4.3(GND3) MTG4.4(GND4) MTG4.5(GND5) MTG4.6(GND6) MTG4.7(GND7) MTG4.8(GND8) MTG4.9(GND9) R251.2 R320.2 R321.1 R526.2 R574.1 R575.1
VDD_1V2: C278.1 FB14.2 FB15.2 U50.5(OUT)
VDD_1V8: C36.1 C45.1 C46.1 C47.1 C56.1 C57.1 C58.1 C59.1 C60.1 C85.1 C87.1 C137.1 C259.1 C323.1 C324.1 C331.1 L5.2 R23.1 R41.1 R42.1 R43.1 R44.1 R45.1 R46.1 R47.1 R48.1 R49.1 R64.1 R65.1 R68.1 R149.1 R153.1 R154.1 R156.1 R157.1 TP10.1(TP) U4.5(OUT) U8.5(VCC) U18.3(VCCA) U18.6(OE) U27.30(VDDD) U45.3(VCCA) U45.6(OE) U55.B4(VCC) U55.D1(VCCQ#D1) U55.E4(VCCQ#E4) Y1.4(VCC/VDD)
VDD_1V8_FB: C36.2 R23.2 R24.1 U4.7(FB)
VDD_1V8_SW: L5.1 U4.3(SW)
VDD_3V3: C37.1 C38.1 C39.1 C40.1 C41.1 C42.1 C65.1 C70.1 C71.1 C88.1 C89.1 C91.1 C100.1 C101.1 C108.1 C109.1 C115.1 C116.1 C121.1 C122.1 C125.1 C133.1 C134.1 C139.1 C140.1 C141.1 C142.1 C143.1 C144.1 C145.1 C153.1 C208.1 C227.1 C253.1 C260.1 C261.1 C262.1 C319.1 D48.2(NC) FB1.1 FB2.2 FB4.1 FB8.1 FB9.1 FB11.1 FB12.1 FB16.2 J4.5 J11.1 L4.2 Q1.1(G) Q6.1(G) Q7.1(G) Q8.1(G) R18.1 R94.1 R103.1 R133.1 R134.1 R135.1 R136.1 R143.1 R145.1 R147.1 R158.1 R159.1 R160.1 R248.1 R266.1 R278.1 R289.1 R300.1 R301.1 R303.2 R304.1 R305.1 R306.1 R308.1 R309.1 R310.1 R311.1 R312.1 R316.1 R318.1 R344.1 R345.1 R360.1 R361.1 R363.1 R379.1 R380.1 R395.1 R396.1 R398.1 R414.1 R416.1 R417.1 R423.1 R424.1 R426.1 R427.1 R428.1 R429.1 R431.1 R432.1 R434.1 R435.1 R437.1 R438.1 R456.1 R460.1 R467.1 R468.1 R470.1 R471.1 R473.1 R474.1 R498.1 R521.1 R539.1 R544.1 R557.1 R558.1 R559.1 R561.1 R563.1 TP9.1(TP) U3.5(OUT) U12.5(VCC) U13.5(VCC) U18.7(VCCB) U20.1(VDD1) U22.1(VDD1) U23.1(VDD1) U25.1(VDD1) U27.20(VDDIO) U28.13(VD33#13) U28.19(VD33#19) U28.27(VD3_IN) U28.32(VD33#32) U28.41(VD33#41) U29.12(VDD) U35.5(VCC) U39.5(VCC) U42.24(VCC) U45.7(VCCB) U46.3(VCCA) U46.6(OE) U46.7(VCCB) U50.1(IN) U54.16(VCC) Y2.4(VCC/VDD)
VDD_3V3_SW: L4.1 U3.3(SW)
VDD_3V9: C177.1 C178.1 C179.1 C180.1 C181.1 C185.1 C186.1 C187.1 C188.1 C189.1 C190.1 C191.1 C192.1 C193.1 C194.1 J19.2(IO_2) J19.4(IO_4) J19.70(IO_70) J19.72(IO_72) J19.74(IO_74) L10.2 R328.1 R336.1 R337.1 R338.1 R339.1 R340.1 R341.1 R342.1 TP17.1(TP)
VDD_5V: C26.1 C27.1 C28.1 C29.1 C30.1 C33.1 C34.1 C35.1 C43.1 C44.1 C83.1 C84.1 C90.1 C92.1 C105.1 C113.1 C157.1 C159.1 C172.1 C173.1 C174.1 C281.1 C325.1 C328.1 C329.1 C330.1 D58.1 D59.1 F2.2 F3.2 J9.1 J11.2 L3.2 R10.1 R13.1 R14.1 R17.1 R21.1 R107.1 R324.1 R530.1 R531.1 TP7.1(TP) U3.2(VIN) U4.2(VIN) U21.2(VIN) U24.2(VIN) U30.5(IN) U31.5(IN) U53.7(VCCB)
VDD_5V_SW: C25.2 L3.1 U2.5(LX1) U2.15(LX2) U2.16(LX3)
VDD_12V: C10.1 C12.1 C13.1 C22.1 C23.1 C24.1 C334.1 C335.1 C336.1 C337.1 FB3.2 R1.1 R2.1 R4.1 R11.1 R117.1 SW1.3 U1.2(IN1) U1.3(IN2) U1.4(IN3) U2.2(IN1) U2.3(IN2) U2.4(IN3)
VDD_12VSW: C1.1 C2.1 C3.1 C4.1 C5.1 C6.1(P) C332.1 C333.1 C338.1 L1.4 SW1.2 TP2.1(TP)
VDD_485_5V: C114.1 C117.1 C118.1 C123.1 C124.1 R267.1 R273.1 R279.1 U23.16(VDD2) U24.4(+VO) U25.16(VDD2)
VDD_AUDIO_3V3: C135.1 C136.1 FB4.2 U27.5(VDDA)
VDD_BAT: D48.1(ANODE) J25.1
VDD_BLE_3V3: C61.1 C62.1 C269.1 C270.1 C271.1 FB2.1 R69.1 R70.1 R71.1 R72.1 R73.1 R74.1 R76.1 R77.1 R511.1 U47.34(VDDIO) U47.36(VBAT) Y6.4(VCC/VDD)
VDD_CAN_5V: C102.1 C103.1 C106.1 C110.1 C111.1 R258.1 U20.8(VDD2) U21.4(+VO) U22.8(VDD2)
VDD_IN: F1.1 J1.4
VDD_IN_GND: D1.1 J1.2 L1.2
VDD_LVD_5V: C73.1 C74.1 C75.1 C76.1 C79.1 C80.1 C256.1 C257.1 C258.1 J5.2(VCC5V#2) J5.3(VCC5V#3) J6.2(VCC5V#2) J6.3(VCC5V#3) J8.1 J8.2 J8.3 Q3.3(D)
VDD_MMC1_SD: C54.1 C55.1 FB1.2 J2.4(VCC) R34.1 R35.1 R36.1 R37.1 R38.1 R39.1 R40.1
VDD_PHY1_1V1: C206.1 C207.1 C211.1 FB10.1 L11.2 U33.22(DVDDL)
VDD_PHY1_3V3: C214.1 C215.1 C216.1 FB9.2 R364.1 R365.1 R370.1 U33.30(DVDD33) U33.31(VDD33_LX)
VDD_PHY2_1V1: C225.1 C226.1 C230.1 FB13.1 L12.2 U37.22(DVDDL)
VDD_PHY2_3V3: C233.1 C234.1 C235.1 FB12.2 R399.1 R400.1 R405.1 U37.30(DVDD33) U37.31(VDD33_LX)
VDD_RTC: C249.1 C250.1 C251.1 D48.3(CATHODE) U40.6(VDD)
VDD_SOM_3V3: R216.1 R217.1 R218.1 R219.1 R220.1 R221.1 R222.1 R223.1 R224.1 R225.1 R226.1 R227.1 R228.1 R229.1 R230.1 R231.1 R573.1 U43.L43
VDD_SOM_5V: R3.1 R536.1 U43.161 U43.162 U43.163 U43.164
VDD_SOM_5V_R: C14.1 C15.1 C16.1 C17.1 C18.1 L2.2 R7.1 R8.1 R536.2
VDD_SOM_5V_SW: C11.2 L2.1 U1.5(LX1) U1.15(LX2) U1.16(LX3)
VDD_USB0_VBUS: C154.1 C155.1 C156.1 C161.1 C162.1 C163.1 C164.1 D22.2 J15.A4(VBUS1) J15.A9(VBUS2) J15.B4(VBUS4) J15.B9(VBUS3) U29.4(VBUS_DET) U30.1(OUT)
VDD_USB_1V8: C148.1 C149.1 C150.1 C151.1 C152.1 FB7.1 U28.3(VD18#3) U28.26(VREG18) U28.29(VD18#29)
VDD_USB_PLL: FB7.2 U28.9(VD_PLL)
VDD_USIM1: J19.36(IO_36) R322.1 R323.1 TP15.1(PIN1)
VDD_USIM2: J19.48(IO_48) R331.1 R334.1
VDDA_PHY1_1V1: C217.1 C218.1 C219.1 FB10.2 U33.4(AVDDL#4) U33.9(AVDDL#9) U33.47(AVDDL#47)
VDDA_PHY1_3V3: C212.1 C213.1 FB8.2 U33.1(AVDD33#1) U33.12(AVDD33#12)
VDDA_PHY2_1V1: C236.1 C237.1 C238.1 FB13.2 U37.4(AVDDL#4) U37.9(AVDDL#9) U37.47(AVDDL#47)
VDDA_PHY2_3V3: C231.1 C232.1 FB11.2 U37.1(AVDD33#1) U37.12(AVDD33#12)
32.7K_CLK: C272.1 R512.2 R513.1 U47.31(LPO)
ANTCTL1: J19.61(IO_61) TP23.1(PIN1)
ANTCTL2: J19.63(IO_63) TP24.1(PIN1)
AP2SDX_STATUS: J19.68(IO_68) R343.1
AUD_MCASP0_ACLKX: R292.1 U54.3(1B2)
AUD_MCASP0_AFSX: R294.1 U54.6(2B2)
AUD_MCASP0_AXR0: R293.1 U54.10(3B2)
AUD_MCASP0_AXR1: R295.1 U54.13(4B2)
AUD_MIC: C127.1 J14.4(MIC) R297.1
AUDIO_GND: C128.2 C129.2 C130.2 C131.2 C132.2 C135.2 C136.2 FB6.2 R298.2 R569.2 R570.2 U27.7(AGND)
AUDIO_I2C_SCL: R290.2 R434.2 U27.29(CTRL_CLK)
AUDIO_I2C_SDA: R291.2 R435.2 U27.27(CTRL_DATA)
AUDIO_LOUT_L: C129.1 CT1.2 J14.1(L)
AUDIO_LOUT_R: C128.1 CT2.2 J14.2(R)
AUDIO_MCLK: R288.2 U27.21(SYS_MCLK)
AUDIO_SEL: JP1.1(E1) R557.2 U54.1(S)
BOOTMODE00: R206.2 R216.2 R232.1
BOOTMODE01: R207.2 R217.2 R233.1
BOOTMODE02: R208.2 R221.2 R234.1
BOOTMODE03: R209.2 R241.1 SW2.8(OFF1)
BOOTMODE04: R210.2 R242.1 SW2.7(OFF2)
BOOTMODE05: R211.2 R243.1 SW2.6(OFF3)
BOOTMODE06: R212.2 R244.1 SW2.5(OFF4)
BOOTMODE07: R213.2 R245.1 SW3.8(OFF1)
BOOTMODE08: R197.2 R246.1 SW3.7(OFF2)
BOOTMODE09: R199.2 R247.1 SW3.6(OFF3)
BOOTMODE10: R200.2 R222.2 R235.1
BOOTMODE11: R201.2 R228.2 R236.1
BOOTMODE12: R202.2 R223.2 R237.1
BOOTMODE13: R203.2 R224.2 R238.1
BOOTMODE14: R204.2 R225.2 R239.1
BOOTMODE15: R205.2 R226.2 R240.1
BT_RST: R73.2 U42.7(P03) U47.49(HOST_WAKE_BT)
CAM_P1_MCLK: R152.2 Y1.3(OUT/OUTPUT)
CAM_RST: R150.2 R154.2 U18.4(A2)
CANH1: D20.2 J13.2 R253.2
CANH2: D18.2 J13.5 R261.2
CANL1: D21.2 J13.1 R254.2
CANL2: D19.2 J13.4 R262.2
CH_UART0_RXD: Q6.3(D) U19.21(TXD0)
CH_UART0_TXD: Q1.2(S) U19.20(RXD0)
CH_UART1_RXD: Q8.3(D) U19.13(TXD1)
CH_UART1_TXD: Q7.2(S) U19.12(RXD1)
CONFIG_0: J19.21(IO_21) R341.2 TP19.1(PIN1)
CONFIG_1: J19.69(IO_69) R340.2 TP27.1(PIN1)
CONFIG_2: J19.75(IO_75) R339.2 TP28.1(PIN1)
CONFIG_3: J19.1(IO_1) R338.2 TP18.1(PIN1)
CSI_PWDN: R151.2 R153.2 U18.5(A1)
CVCC_1V2: C282.1 C283.1 C284.1 C285.1 C286.1 C287.1 FB14.1 U48.5(CVCC12#5) U48.12(CVCC12#12) U48.26(CVCC12#26) U48.42(CVCC12#42) U48.47(CVCC12#47) U48.53(CVCC12#53)
DEBUG_USB_CC1: D12.2 J12.A5(CC1) R249.1
DEBUG_USB_CC2: D13.2 J12.B5(CC2) R250.1
DEBUG_USB_DM: D10.2 J12.A7(DN1) J12.B7(DN2) L6.2
DEBUG_USB_DP: D11.2 J12.A6(DP1) J12.B6(DP2) L6.3
DEBUG_VBUS_5V: C93.1 C94.1 C95.1 C97.1 D9.2 J12.A4(VBUS1) J12.A9(VBUS2) J12.B4(VBUS4) J12.B9(VBUS3) U19.7(VDD5) U19.8(VBUS)
DRP: J19.25(IO_25) TP21.1(PIN1)
DS: R49.2 R50.2 R62.1 U55.C3(DS)
EN_VDD_3V3: C320.1 R17.2 R19.1 R573.2 U3.8(EN)
ETH1_CONFIG_LDO0: R365.2 R367.1 U33.36(LED1/CFG_LDO0)
ETH1_LED_ACT: D41.2 J22.12(YELLOW-) R370.2 R373.1 U33.35(LED0/PHYAD0)
ETH1_LED_LINK: D40.2 J22.14(GREEN-) R364.2 R366.1 U33.37(LED2/CFG_LDO1)
ETH1_MD1_N: J22.2(TD1-) U32.6(D1-) U33.3(TRXN0)
ETH1_MD1_P: J22.1(TD1+) U32.1(D1+) U33.2(TPXP0)
ETH1_MD2_N: J22.4(TD2-) U32.4(D2-) U33.6(TRXN1)
ETH1_MD2_P: J22.3(TD2+) U32.3(D2+) U33.5(TRXP1)
ETH1_MD3_N: J22.8(TD3-) U33.8(TRXN2) U34.6(D1-)
ETH1_MD3_P: J22.7(TD3+) U33.7(TRXP2) U34.1(D1+)
ETH1_MD4_N: J22.10(TD4-) U33.11(TRXN3) U34.4(D2-)
ETH1_MD4_P: J22.9(TD4+) U33.10(TRXP3) U34.3(D2+)
ETH1_MRSTN: R361.2 U35.1(B) U42.9(P05)
ETH1_RST: R25.1 R363.2 U33.13(RESET_N) U35.4(Y)
ETH1_XTAL_I: C201.1 U33.45(XTAL_I) Y4.1
ETH1_XTAL_O: C205.1 U33.46(XTAL_O/EXT_CLK) Y4.3
ETH2_CONFIG_LDO0: R400.2 R402.1 U37.36(LED1/CFG_LDO0)
ETH2_LED_ACT: D43.2 J23.12(YELLOW-) R405.2 R408.1 U37.35(LED0/PHYAD0)
ETH2_LED_LINK: D42.2 J23.14(GREEN-) R399.2 R401.1 U37.37(LED2/CFG_LDO1)
ETH2_MD1_N: J23.2(TD1-) U36.6(D1-) U37.3(TRXN0)
ETH2_MD1_P: J23.1(TD1+) U36.1(D1+) U37.2(TPXP0)
ETH2_MD2_N: J23.4(TD2-) U36.4(D2-) U37.6(TRXN1)
ETH2_MD2_P: J23.3(TD2+) U36.3(D2+) U37.5(TRXP1)
ETH2_MD3_N: J23.8(TD3-) U37.8(TRXN2) U38.6(D1-)
ETH2_MD3_P: J23.7(TD3+) U37.7(TRXP2) U38.1(D1+)
ETH2_MD4_N: J23.10(TD4-) U37.11(TRXN3) U38.4(D2-)
ETH2_MD4_P: J23.9(TD4+) U37.10(TRXP3) U38.3(D2+)
ETH2_MRSTN: R396.2 U39.1(B) U42.10(P06)
ETH2_RST: R26.1 R398.2 U37.13(RESET_N) U39.4(Y)
ETH2_XTAL_I: C220.1 U37.45(XTAL_I) Y5.1
ETH2_XTAL_O: C224.1 U37.46(XTAL_O/EXT_CLK) Y5.3
FPC_LVDS0_A0N: J6.8(RXIN0-) R118.2
FPC_LVDS0_A0P: J6.9(RXIN0+) R110.2
FPC_LVDS0_A1N: J6.11(RXIN1-) R113.2
FPC_LVDS0_A1P: J6.12(RXIN1+) R115.2
FPC_LVDS0_A2N: J6.14(RXIN2-) R119.2
FPC_LVDS0_A2P: J6.15(RXIN2+) R121.2
FPC_LVDS0_A3N: J6.20(RXIN3-) R128.2
FPC_LVDS0_A3P: J6.21(RXIN3+) R130.2
FPC_LVDS0_CLK0N: J6.17(RXXLK-) R123.2
FPC_LVDS0_CLK0P: J6.18(RXCLK+) R125.2
FPC_LVDS1_A0N: J5.8(RXIN0-) R109.2
FPC_LVDS1_A0P: J5.9(RXIN0+) R111.2
FPC_LVDS1_A1N: J5.11(RXIN1-) R114.2
FPC_LVDS1_A1P: J5.12(RXIN1+) R116.2
FPC_LVDS1_A2N: J5.14(RXIN2-) R120.2
FPC_LVDS1_A2P: J5.15(RXIN2+) R122.2
FPC_LVDS1_A3N: J5.20(RXIN3-) R129.2
FPC_LVDS1_A3P: J5.21(RXIN3+) R131.2
FPC_LVDS1_CLK0N: J5.17(RXXLK-) R124.2
FPC_LVDS1_CLK0P: J5.18(RXCLK+) R126.2
FULL_CARD_POWR_OFF_N: J19.6(IO_6) R337.2
HDMI_CLK+: U48.59(TXC+) U52.C3(CH2_OUT+)
HDMI_CLK-: U48.58(TXC-) U52.C4(CH2_OUT-)
HDMI_CONN_CLKN: J29.12(CLK-) U52.A4(CH2_IN-)
HDMI_CONN_CLKP: J29.10(CLK+) U52.A3(CH2_IN+)
HDMI_CONN_SCL: J29.15(SCL) R522.2 R530.2 U53.8(B1)
HDMI_CONN_SDA: J29.16(SDA) R523.2 R531.2 U53.1(B2)
HDMI_CONN_TX0N: J29.9(D0-) U52.A2(CH1_IN-)
HDMI_CONN_TX0P: J29.7(D0+) U52.A1(CH1_IN+)
HDMI_CONN_TX1N: J29.6(D1-) U51.A4(CH2_IN-)
HDMI_CONN_TX1P: J29.4(D1+) U51.A3(CH2_IN+)
HDMI_CONN_TX2N: J29.3(D2-) U51.A2(CH1_IN-)
HDMI_CONN_TX2P: J29.1(D2+) U51.A1(CH1_IN+)
HDMI_HPD: Q2.2(E) R527.1 U48.54(HPD)
HDMI_I2C_SCL: R529.2 R532.1 U48.49(DSCL)
HDMI_I2C_SDA: R528.2 R533.1 U48.48(DSDA)
HDMI_MCASP0_ACLKX: R161.1 U54.2(1B1)
HDMI_MCASP0_AFSX: R162.1 U54.5(2B1)
HDMI_MCASP0_AXR: R516.1 U54.11(3B1)
HDMI_MCLK: R534.2 U48.38(MCLK)
HDMI_TX0+: U48.62(TX0+) U52.C1(CH1_OUT+)
HDMI_TX0-: U48.61(TX0-) U52.C2(CH1_OUT-)
HDMI_TX1+: U48.65(TX1+) U51.C3(CH2_OUT+)
HDMI_TX1-: U48.64(TX1-) U51.C4(CH2_OUT-)
HDMI_TX2+: U48.68(TX2+) U51.C1(CH1_OUT+)
HDMI_TX2-: U48.67(TX2-) U51.C2(CH1_OUT-)
HP_L: CT1.1 U27.6(HP_L)
HP_R: CT2.1 U27.2(HP_R)
HP_VGND: R298.1 U27.4(HP_VGND)
HPD_DET: J29.19(HOTPLUG) R524.1 R525.1
I2C_SCL_CSI: R428.2 R452.2 U45.8(B1)
I2C_SCL_CSI_1V8: J9.5 R156.2 U45.5(A1)
I2C_SDA_CSI: R429.2 R444.2 U45.1(B2)
I2C_SDA_CSI_1V8: J9.4 R157.2 U45.4(A2)
I2S_DIN: R293.2 U27.26(I2S_DIN)
I2S_DOUT: R295.2 U27.25(I2S_DOUT)
I2S_LRCLK: R294.2 U27.23(I2S_LRCLK)
I2S_SCLK: R292.2 U27.24(I2S_SCLK)
IOVCC_3V3: C280.1 C288.1 C289.1 C290.1 C293.1 FB16.1 Q2.3(C) R433.1 R514.1 R528.1 R529.1 R535.1 R537.1 U48.3(IOVCC#3) U48.21(IOVCC#21) U48.46(IOVCC#46) U53.3(VCCA) U53.6(OE) Y7.4(VCC/VDD)
ISO_485: C114.2 C117.2 C118.2 C119.2 C123.2 C124.2 D14.1 D15.1 D16.1 D17.1 J13.7 J13.10 R273.2 R275.2 R277.2 R286.2 U23.9(GND2#9) U23.10(GND2#10) U23.15(GND2#15) U24.3(0V) U25.9(GND2#9) U25.10(GND2#10) U25.15(GND2#15)
ISO_CAN: C102.2 C103.2 C104.2 C106.2 C107.2 C110.2 C111.2 C112.2 D18.1 D19.1 D20.1 D21.1 J13.3 J13.6 R258.2 R259.2 U20.5(GND2) U21.3(0V) U22.5(GND2)
JTAG_CTI_RTCK: J4.9 R105.2
JTAG_CTI_TCK: J4.11 R103.2 R106.1 U12.1(A) U13.1(A)
JTAG_EMU_RSTN: R540.1 U43.45
JTAG_EMU_RSTN_R: J4.15 R94.2 R540.2
JTAG_TDIS: J4.4 R92.1
LAA_TX_EN: J19.59(IO_59) TP22.1(PIN1)
LCD_B0: R163.2 U48.32(VDATA_IN0)
LCD_B1: R164.2 U48.31(VDATA_IN1)
LCD_B2: R165.2 U48.30(VDATA_IN2)
LCD_B3: R166.2 U48.29(VDATA_IN3)
LCD_B4: R167.2 U48.28(VDATA_IN4)
LCD_B5: R168.2 U48.27(VDATA_IN5)
LCD_B6: R169.2 U48.25(VDATA_IN6)
LCD_B7: R170.2 U48.24(VDATA_IN7)
LCD_DE: R194.2 U48.33(DE)
LCD_G0: R171.2 U48.23(VDATA_IN8)
LCD_G1: R172.2 U48.20(VDATA_IN9)
LCD_G2: R173.2 U48.19(VDATA_IN10)
LCD_G3: R174.2 U48.18(VDATA_IN11)
LCD_G4: R175.2 U48.17(VDATA_IN12)
LCD_G5: R176.2 U48.16(VDATA_IN13)
LCD_G6: R177.2 U48.15(VDATA_IN14)
LCD_G7: R178.2 U48.14(VDATA_IN15)
LCD_HSYNC: R196.2 U48.34(HSYNC)
LCD_I2C_SCL: R431.2 R445.2 U48.1(CSCL)
LCD_I2C_SDA: R432.2 R489.2 U48.2(CSDA)
LCD_PCLK: R198.2 U48.22(IDCK)
LCD_R0: R179.2 U48.13(VDATA_IN16)
LCD_R1: R180.2 U48.11(VDATA_IN17)
LCD_R2: R181.2 U48.10(VDATA_IN18)
LCD_R3: R182.2 U48.9(VDATA_IN19)
LCD_R4: R183.2 U48.8(VDATA_IN20)
LCD_R5: R184.2 U48.7(VDATA_IN21)
LCD_R6: R185.2 U48.6(VDATA_IN22)
LCD_R7: R186.2 U48.4(VDATA_IN23)
LCD_TP_INTN: R190.1 U42.4(P00)
LCD_TP_INTN_R: R190.2 R433.2 U48.52(INT)
LCD_TP_RESET: R191.1 U42.5(P01)
LCD_TP_RESET_R: R191.2 R537.2 U48.51(RESETN)
LCD_VSYNC: R195.2 U48.35(VSYNC)
LVDS0_CLKN: J8.15 U16.A4(CH2_IN-)
LVDS0_CLKP: J8.16 U16.A3(CH2_IN+)
LVDS0_D0N: J8.7 U14.A2(CH1_IN-)
LVDS0_D0P: J8.8 U14.A1(CH1_IN+)
LVDS0_D1N: J8.9 U14.A4(CH2_IN-)
LVDS0_D1P: J8.10 U14.A3(CH2_IN+)
LVDS0_D2N: J8.11 U16.A2(CH1_IN-)
LVDS0_D2P: J8.12 U16.A1(CH1_IN+)
LVDS0_D3N: J8.17 U16.A6(CH3_IN-)
LVDS0_D3P: J8.18 U16.A5(CH3_IN+)
LVDS0_I2C_SCL: J6.34(TP_SCK) R438.2 R491.2
LVDS0_I2C_SDA: J6.33(TP_MOSI) R437.2 R449.2
LVDS0_TP_PEN: JP2.2(E2) R143.2 R144.1
LVDS1_CLKN: J8.27 U17.A4(CH2_IN-)
LVDS1_CLKP: J8.28 U17.A3(CH2_IN+)
LVDS1_D0N: J8.19 U15.A2(CH1_IN-)
LVDS1_D0P: J8.20 U15.A1(CH1_IN+)
LVDS1_D1N: J8.21 U15.A4(CH2_IN-)
LVDS1_D1P: J8.22 U15.A3(CH2_IN+)
LVDS1_D2N: J8.23 U17.A2(CH1_IN-)
LVDS1_D2P: J8.24 U17.A1(CH1_IN+)
LVDS1_D3N: J8.29 U17.A6(CH3_IN-)
LVDS1_D3P: J8.30 U17.A5(CH3_IN+)
LVDS1_I2C_SCL: J5.34(TP_SCK) R451.2 R467.2
LVDS1_I2C_SDA: J5.33(TP_MOSI) R468.2 R492.2
LVDS1_TP_PEN: JP3.2(E2) R145.2 R146.1
MCLK_12M: R534.1 Y7.3(OUT/OUTPUT)
MIC_BIAS: C130.1 R297.2 U27.16(MIC_BIAS)
MIC_IN: C127.2 U27.15(MIC)
MODULE_RESET_N: C200.1 J19.67(IO_67) TP26.1(PIN1)
OSPI_CLK: R51.1 R66.1 U55.B2(CK)
OSPI_CS: R54.1 R65.2 U55.C2(C\S\)
OSPI_DQ0: R41.2 R52.1 U55.D3(DQ0)
OSPI_DQ1: R42.2 R53.1 U55.D2(DQ1)
OSPI_DQ2: R43.2 R55.1 U55.C4(DQ2)
OSPI_DQ3: R44.2 R56.1 U55.D4(DQ3)
OSPI_DQ4: R45.2 R58.1 U55.D5(DQ4)
OSPI_DQ5: R46.2 R59.1 U55.E3(DQ5)
OSPI_DQ6: R47.2 R60.1 U55.E2(DQ6)
OSPI_DQ7: R48.2 R61.1 U55.E1(DQ7)
OSPI_INTN: R57.1 R64.2 U55.A5(I\N\T\)
OSPI_RSTN: R68.2 U8.4(Y) U55.A4(R\E\S\E\T\)
PG_VDD_3V3: R21.2 R22.1 R544.2 U3.1(PG) U4.8(EN)
RFFE_VIO_1V8: J19.65(IO_65) TP25.1(PIN1)
RS485_A1: D17.2 J13.8 R270.2 R271.1
RS485_A2: D15.2 J13.11 R281.2 R282.1
RS485_B1: D16.2 J13.9 R271.2 R272.2
RS485_B2: D14.2 J13.12 R282.2 R284.2
RTC_I2C_SCL: R453.2 R470.2 U40.2(SCL)
RTC_I2C_SDA: R471.2 R493.2 U40.13(SDA)
SDX2AP_STATUS: J19.38(IO_38) R342.2
SEL_XDS110_INV: J4.8 U12.2(B) U13.2(B)
SOC_CSI0_RXCLKN: J9.18 U43.47
SOC_CSI0_RXCLKP: J9.17 U43.46
SOC_CSI0_RXN0: J9.24 U43.50
SOC_CSI0_RXN1: J9.21 U43.53
SOC_CSI0_RXN2: J9.15 U43.56
SOC_CSI0_RXN3: J9.12 U43.59
SOC_CSI0_RXP0: J9.23 U43.49
SOC_CSI0_RXP1: J9.20 U43.52
SOC_CSI0_RXP2: J9.14 U43.55
SOC_CSI0_RXP3: J9.11 U43.58
SOC_EXT_REFCLK1: J7.4 R147.2 U43.L22
SOC_EXTINT_GPIO1_31: R498.2 U42.1(INT_N) U43.42
SOC_GPMC0_AD0/BOOTMODE00: J11.6 R206.1 U43.118
SOC_GPMC0_AD1/BOOTMODE01: J11.8 R207.1 U43.110
SOC_GPMC0_AD2/BOOTMODE02: J11.10 R208.1 U43.111
SOC_GPMC0_AD3/BOOTMODE03: J11.12 R209.1 U43.114
SOC_GPMC0_AD4/BOOTMODE04: J11.16 R210.1 U43.104
SOC_GPMC0_AD5/BOOTMODE05: J11.18 R211.1 U43.L37
SOC_GPMC0_AD6/BOOTMODE06: J11.20 R212.1 U43.L38
SOC_GPMC0_AD7/BOOTMODE07: J11.22 R213.1 U43.L36
SOC_GPMC0_ADVN_ALE: J11.17 U43.L48
SOC_GPMC0_BE0N_CLE: J11.21 U43.L34
SOC_GPMC0_BE1N: C247.1 C248.1 D49.2 R417.2 S3.3 S3.4 U43.L39
SOC_GPMC0_CLK: J11.5 U43.120
SOC_GPMC0_CSN0: J11.7 U43.L47
SOC_GPMC0_DIR: J11.19 R572.1 U43.L33
SOC_GPMC0_OEN_REN: J11.11 U43.L40
SOC_GPMC0_WAIT0: J11.15 R571.1 U43.L35
SOC_GPMC0_WAIT1: R269.1 U43.L32
SOC_GPMC0_WEN: J11.9 U43.L42
SOC_GPMC0_WPN: R268.1 U43.L41
SOC_I2C1_SCL: R192.1 U43.122
SOC_I2C1_SCL_R: R460.2 R461.2 U42.22(SCL)
SOC_I2C1_SDA: R141.1 R449.1 U43.121
SOC_I2C1_SDA_R: R141.2 R456.2 U42.23(SDA)
SOC_JTAG_EMU0: J4.13 U43.160
SOC_JTAG_EMU1: J4.14 U43.150
SOC_JTAG_TCK: R104.2 U43.6
SOC_JTAG_TDI: J4.3 U43.4
SOC_JTAG_TDO: J4.7 U43.7
SOC_JTAG_TMS: J4.1 U43.8
SOC_JTAG_TRSTN: J4.2 U43.5
SOC_LVDS0_A0N: R118.1 U14.C2(CH1_OUT-) U43.11
SOC_LVDS0_A0P: R110.1 U14.C1(CH1_OUT+) U43.10
SOC_LVDS0_A1N: R113.1 U14.C4(CH2_OUT-) U43.14
SOC_LVDS0_A1P: R115.1 U14.C3(CH2_OUT+) U43.13
SOC_LVDS0_A2N: R119.1 U16.C2(CH1_OUT-) U43.17
SOC_LVDS0_A2P: R121.1 U16.C1(CH1_OUT+) U43.16
SOC_LVDS0_A3N: R128.1 U16.C6(CH3_OUT-) U43.20
SOC_LVDS0_A3P: R130.1 U16.C5(CH3_OUT+) U43.19
SOC_LVDS0_CLK0N: R123.1 U16.C4(CH2_OUT-) U43.23
SOC_LVDS0_CLK0P: R125.1 U16.C3(CH2_OUT+) U43.22
SOC_LVDS1_A0N: R109.1 U15.C2(CH1_OUT-) U43.26
SOC_LVDS1_A0P: R111.1 U15.C1(CH1_OUT+) U43.25
SOC_LVDS1_A1N: R114.1 U15.C4(CH2_OUT-) U43.29
SOC_LVDS1_A1P: R116.1 U15.C3(CH2_OUT+) U43.28
SOC_LVDS1_A2N: R120.1 U17.C2(CH1_OUT-) U43.32
SOC_LVDS1_A2P: R122.1 U17.C1(CH1_OUT+) U43.31
SOC_LVDS1_A3N: R129.1 U17.C6(CH3_OUT-) U43.35
SOC_LVDS1_A3P: R131.1 U17.C5(CH3_OUT+) U43.34
SOC_LVDS1_CLK0N: R124.1 U17.C4(CH2_OUT-) U43.38
SOC_LVDS1_CLK0P: R126.1 U17.C3(CH2_OUT+) U43.37
SOC_MCASP0_ACLKX: U43.L13 U54.4(1A)
SOC_MCASP0_AFSX: U43.L14 U54.7(2A)
SOC_MCASP0_AXR0: U43.L15 U54.9(3A)
SOC_MCASP0_AXR1: U43.L16 U54.12(4A)
SOC_MCU_MCAN0_RX: R257.1 U43.L57
SOC_MCU_MCAN0_TX: R252.1 U43.L54
SOC_MCU_MCAN1_RX: D53.2(K) U43.L55
SOC_MCU_MCAN1_TX: R77.2 U43.L56 U47.15(WL_REG_ON)
